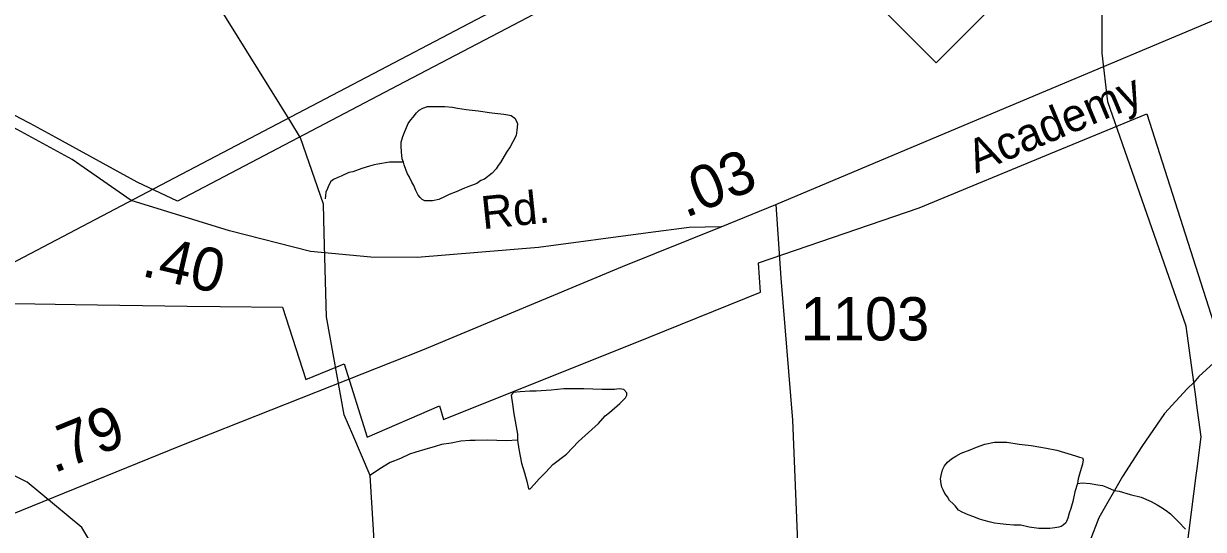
# Model space of a CAD drawing. Extents: x 2001466 to 2224147, y 644118 to 847247.
# Drawn here: x 2052246 to 2055654, y 665696 to 667157 of the extents above; entities that cross this region are included whole.
import ezdxf

# ---------------------------------------------------------------- set-up
doc = ezdxf.new("R2010")
doc.units = 0
for name, color, linetype in [('Exist Boundary Political City Limit New', 7, 'Continuous'), ('Exist Hydrographic Creek Single Shore', 7, 'Continuous'), ('Exist Hydrographic Misc Water Feature', 7, 'Continuous'), ('Exist Railroad Mainline', 7, 'Continuous'), ('Exist Road Primary NC Attributed', 7, 'Continuous'), ('Exist Road Primary NC Label', 7, 'Continuous'), ('Exist Road Primary NC Service Mileage Hundredths English Label', 7, 'Continuous'), ('Exist Road Primary NC Shield CELL', 7, 'Continuous'), ('Exist Road Secondary Mileage Hundredths English Label', 7, 'Continuous'), ('Exist Road Secondary Type 51 Attributed', 7, 'Continuous'), ('Exist Road Secondary Type 51 Label', 7, 'Continuous'), ('Exist Road Secondary Type 51 Number Label', 7, 'Continuous'), ('Map Preparation Boundary City Limit Buffer Line', 7, 'Continuous')]:
    doc.layers.add(name, color=color, linetype=linetype)

msp = doc.modelspace()

# ---------------------------------------------------------------- linework, layer by layer
at = {"layer": 'Exist Boundary Political City Limit New'}
for points in [[(2054801.8, 667751.5), (2053660.4, 667152.6), (2053327.5, 666977.9), (2052690.6, 666643.7), (2052574.2, 666699.1), (2052338.9, 666828.2), (2052265, 666867.9), (2052235.1, 666884), (2052099.1, 666957.6), (2052098.8, 666888.7), (2052095.1, 666691.8)], [(2052095.1, 666691.8), (2052092, 666502.8), (2052090.8, 666445.9), (2052123.5, 666350), (2052220.5, 666348.5), (2052394.6, 666345.8), (2052718.4, 666340.8), (2052814, 666339.7), (2052993.8, 666337.4), (2053061.5, 666128.9), (2053171.9, 666173.9), (2053238.5, 665962.8), (2053447.8, 666053.3), (2053459.1, 666013.7), (2054053.1, 666251.2), (2054374.5, 666381.3), (2054368.9, 666466.1), (2054832.8, 666624.4), (2055228.8, 666788.4), (2055490.1, 666895.9), (2055727.8, 666155.1)]]:
    msp.add_lwpolyline(points, dxfattribs=at)
at = {"layer": 'Exist Hydrographic Creek Single Shore'}
for points in [[(2053017.7, 666872.7), (2052736.4, 667325.2), (2052319.3, 667793), (2052143.4, 668082), (2051868.4, 668350), (2051451.4, 668630.9), (2051117.3, 668781.9), (2050292.4, 668952.9), (2050134.3, 669028.3), (2049975.4, 669271), (2049847.4, 669402.6)], [(2053114.6, 666551.6), (2053112.3, 666635.1), (2053046.3, 666826.8), (2053017.7, 666872.7)], [(2053273.2, 665427.7), (2053006.3, 665420.1), (2052782.4, 665359), (2052490.4, 665574.9), (2052414.3, 665701.1), (2052256.4, 665832.3), (2052022.2, 665948.5), (2051756.3, 665950.7), (2051539.3, 665974.8), (2051155.3, 666107.3), (2050197.3, 666481), (2049997.3, 666488.4), (2049843.6, 666575.6)], [(2053197.2, 665968.7), (2053172.4, 666027), (2053121.3, 666310.1), (2053114.6, 666551.6)], [(2053273.2, 665427.7), (2053247.2, 665851.5), (2053197.2, 665968.7)]]:
    msp.add_lwpolyline(points, dxfattribs=at)
at = {"layer": 'Exist Hydrographic Misc Water Feature'}
for p, q in [((2055632.7, 666072.1), (2055607.1, 666261.8)), ((2055634.1, 666061.9), (2055632.7, 666072.1)), ((2055633.2, 665852), (2055635.7, 665871.8))]:
    msp.add_line(p, q, dxfattribs=at)
for points in [[(2055607.1, 666261.8), (2055604.3, 666282.6), (2055378.3, 666930.3), (2055361.3, 667071.7), (2055367.4, 668505.3), (2055335.1, 668528.9)], [(2053343.2, 666756.6), (2053339.3, 666766.6), (2053337.2, 666786.6), (2053337, 666802.6), (2053337, 666814.6), (2053341.1, 666830.7), (2053345, 666840.7), (2053356.9, 666868.6), (2053364.9, 666878.7), (2053370.9, 666886.7), (2053380.9, 666898.7), (2053388.9, 666906.7), (2053398.9, 666912.8), (2053412.9, 666916.8), (2053436.9, 666916.8), (2053462.7, 666916.8), (2053484.9, 666914.9), (2053499, 666912.9), (2053524.8, 666908.9), (2053558.9, 666905), (2053598.9, 666899.1), (2053632.9, 666895.2), (2053645, 666893.2), (2053654.8, 666891.2), (2053664.9, 666883.3), (2053669, 666877.3), (2053672.9, 666867.3), (2053670.8, 666849.3), (2053669, 666833.3), (2053659.2, 666815.3), (2053651.2, 666801.2), (2053641.1, 666785.2), (2053623.3, 666755.2), (2053617.1, 666747.2), (2053611.2, 666737.2), (2053599.3, 666725.2), (2053577.1, 666707.1), (2053567.1, 666703.1), (2053555.4, 666695.1), (2053539.4, 666689), (2053529.4, 666685), (2053519.3, 666681), (2053495.3, 666671), (2053475.2, 666662.9), (2053463.3, 666656.9), (2053445.3, 666648.9), (2053427.4, 666644.8), (2053415.3, 666644.8), (2053405.5, 666644.8), (2053397.5, 666648.8), (2053391.4, 666654.8), (2053385.4, 666660.8), (2053379.3, 666674.8), (2053373.3, 666688.8), (2053367.4, 666698.7), (2053359.4, 666714.7), (2053355.3, 666722.7), (2053351.2, 666732.7), (2053345.2, 666748.7), (2053343.2, 666756.6)], [(2053343.2, 666756.6), (2053303.2, 666756.6), (2053269.1, 666750.5), (2053259.1, 666748.5), (2053245.2, 666744.5), (2053223.2, 666738.4), (2053197.4, 666728.4), (2053185.3, 666726.4), (2053163.3, 666716.3), (2053153.3, 666712.3), (2053141.4, 666706.3), (2053133.4, 666700.2), (2053127.3, 666690.2), (2053123.4, 666680.3), (2053119.5, 666670.3), (2053117.4, 666650.3)], [(2053672.5, 665953.4), (2053676.6, 665927.5), (2053684.6, 665887.5), (2053692.8, 665859.5), (2053700.8, 665831.5), (2053704.9, 665813.5), (2053708.8, 665813.5), (2053720.9, 665825.5), (2053734.8, 665841.6), (2053754.7, 665861.6), (2053774.6, 665883.6), (2053814.6, 665913.7), (2053848.6, 665949.8), (2053906.4, 666001.8), (2053926.3, 666023.9), (2053938.4, 666033.9), (2053968.4, 666060), (2053984.4, 666076), (2053988.3, 666084), (2053988.3, 666090), (2053980.3, 666100), (2053966.3, 666102), (2053952.4, 666099.9), (2053916.3, 666099.9), (2053864.2, 666101.7), (2053824.2, 666101.7), (2053806.4, 666101.6), (2053770.3, 666097.6), (2053726.2, 666095.5), (2053708.4, 666095.4), (2053680.3, 666093.4), (2053660.4, 666091.4), (2053654.4, 666083.4), (2053658.3, 666057.4), (2053662.4, 666029.4), (2053672.5, 665971.4), (2053672.5, 665953.4)], [(2055635.7, 665871.8), (2055647.3, 665963.5), (2055634.1, 666061.9)], [(2053672.5, 665953.4), (2053640.5, 665951.4), (2053584.7, 665953.3), (2053550.7, 665953.2), (2053534.7, 665953.2), (2053508.6, 665951.1), (2053480.8, 665945.1), (2053452.7, 665941), (2053434.6, 665935), (2053404.7, 665926.9), (2053378.6, 665918.9), (2053360.6, 665912.9), (2053334.8, 665900.8), (2053304.8, 665888.8), (2053274.9, 665870.7), (2053245, 665850.6)], [(2055290.5, 665828.5), (2055282.6, 665804.5), (2055276.6, 665776.5), (2055270.7, 665756.4), (2055266.6, 665742.4), (2055262.7, 665728.5), (2055258.6, 665718.5), (2055256.7, 665714.5), (2055248.7, 665708.4), (2055242.8, 665704.4), (2055236.8, 665702.4), (2055224.7, 665700.4), (2055210.8, 665698.4), (2055198.7, 665698.3), (2055178.8, 665698.3), (2055150.7, 665702.3), (2055126.7, 665708.2), (2055106.8, 665708.2), (2055084.7, 665710.1), (2055066.8, 665712.1), (2055050.8, 665714), (2055034.8, 665718), (2055020.7, 665722), (2055006.8, 665726), (2054990.8, 665731.9), (2054974.8, 665737.9), (2054956.7, 665745.9), (2054946.7, 665751.9), (2054936.6, 665763.9), (2054930.7, 665769.8), (2054920.6, 665779.8), (2054914.7, 665789.8), (2054906.7, 665799.8), (2054902.6, 665809.8), (2054898.7, 665817.8), (2054896.4, 665827.7), (2054894.6, 665841.7), (2054896.4, 665851.7), (2054900.5, 665867.7), (2054906.5, 665879.7), (2054914.5, 665889.7), (2054926.4, 665899.8), (2054938.5, 665907.8), (2054954.5, 665915.9), (2054980.3, 665925.9), (2054998.4, 665933.9), (2055022.3, 665942), (2055050.2, 665948), (2055086.3, 665948.1), (2055122.2, 665942.1), (2055156.2, 665938.2), (2055200.3, 665930.3), (2055230.3, 665924.4), (2055284.4, 665908.4), (2055296.5, 665904.5), (2055304.5, 665902.5), (2055306.3, 665896.5), (2055304.5, 665884.5), (2055298.3, 665862.5), (2055292.6, 665842.5), (2055290.5, 665828.5)], [(2055635.4, 664865.6), (2055590.3, 664924.6), (2055532.3, 665057.1), (2055633.2, 665852)], [(2055290.5, 665828.5), (2055304.5, 665830.5), (2055326.4, 665828.6), (2055348.6, 665824.6), (2055362.5, 665822.6), (2055376.5, 665816.6), (2055396.6, 665808.7), (2055410.5, 665806.7), (2055442.5, 665796.7), (2055474.5, 665788.8), (2055502.6, 665776.9), (2055520.4, 665766.9), (2055530.5, 665761), (2055546.7, 665751), (2055558.6, 665741), (2055566.5, 665733), (2055572.7, 665727), (2055580.7, 665719.1), (2055602.6, 665697.1)]]:
    msp.add_lwpolyline(points, dxfattribs=at)
at = {"layer": 'Exist Railroad Mainline'}
for points in [[(2046464.5, 663426.2), (2046524.6, 663459.1), (2048551.7, 664535.4), (2049194.6, 664876.7), (2049524.4, 665051.8), (2049557.2, 665070.3), (2052622.8, 666680.7), (2055671.2, 668278.9), (2056997.6, 668963.3), (2058840.6, 669936.5)], [(2055727.1, 666216.2), (2055641.1, 666137.7), (2055626.1, 666120.2), (2055607.5, 666101.5), (2055541.4, 666030.4), (2055476, 665935.1), (2055420, 665849.1), (2055352.2, 665729.1), (2055300.2, 665594.9)]]:
    msp.add_lwpolyline(points, dxfattribs=at)
at = {"layer": 'Exist Road Primary NC Attributed'}
for points in [[(2054418.6, 666634.2), (2054907.9, 666840.5), (2055677.6, 667164.1), (2056184.6, 667373.6), (2056567.7, 667530.7), (2056727.8, 667592.5), (2056935, 667655.3), (2057139.1, 667701.4)], [(2054260.6, 666569.3), (2054418.6, 666634.2)], [(2050426, 664989), (2050469.1, 665011), (2050704.3, 665125.3), (2051044.1, 665262.3), (2051844.1, 665591.2), (2052698.6, 665937.8), (2053399.3, 666214.3), (2053976.4, 666455.2), (2054260.6, 666569.3)]]:
    msp.add_lwpolyline(points, dxfattribs=at)
at = {"layer": 'Exist Road Primary NC Shield CELL'}
msp.add_lwpolyline([(2054549.1, 667376.3), (2054882.1, 667709.3), (2055215.1, 667376.3), (2054882.1, 667043.3)], close=True, dxfattribs=at)
at = {"layer": 'Exist Road Secondary Type 51 Attributed'}
for points in [[(2052557.1, 666646.2), (2052386.3, 666764), (2052162.5, 666885.4), (2051899.2, 667023.8), (2051726.1, 667110.4), (2051482.2, 667211.8), (2051238.9, 667288.9), (2050792.4, 667405.1), (2050170.2, 667573.1), (2049959.6, 667625.9), (2049883.6, 667635.4), (2049783.3, 667640.7), (2049542.6, 667618.5), (2049242.3, 667606.9)], [(2054418.6, 666634.2), (2054432.9, 666421.6), (2054466.7, 666011.7), (2054484.6, 665587.1), (2054486.7, 665225.8), (2054483.6, 665090.6), (2054443.4, 664991.3), (2054312.6, 664780.1), (2054253.4, 664718.8), (2053998, 664560.4), (2053751, 664429.4), (2053496.5, 664373.7), (2053164.1, 664331.2), (2052683.1, 664272.6), (2052013.9, 664187.6)], [(2054260.6, 666569.3), (2054168.1, 666567.5), (2054049.9, 666552.7), (2053733.2, 666510.4), (2053382.8, 666480.9), (2053249.3, 666481.9), (2053075.1, 666498.8), (2052840.7, 666558), (2052557.1, 666646.2)]]:
    msp.add_lwpolyline(points, dxfattribs=at)
at = {"layer": 'Map Preparation Boundary City Limit Buffer Line'}
for points in [[(2054801.8, 667751.5), (2053660.4, 667152.6), (2053327.5, 666977.9), (2052690.6, 666643.7), (2052574.2, 666699.1), (2052338.9, 666828.2), (2052265, 666867.9), (2052235.1, 666884), (2052099.1, 666957.6), (2052098.8, 666888.7), (2052095.1, 666691.8)], [(2052095.1, 666691.8), (2052092, 666502.8), (2052090.8, 666445.9), (2052123.5, 666350), (2052220.5, 666348.5), (2052394.6, 666345.8), (2052718.4, 666340.8), (2052814, 666339.7), (2052993.8, 666337.4), (2053061.5, 666128.9), (2053171.9, 666173.9), (2053238.5, 665962.8), (2053447.8, 666053.3), (2053459.1, 666013.7), (2054053.1, 666251.2), (2054374.5, 666381.3), (2054368.9, 666466.1), (2054832.8, 666624.4), (2055228.8, 666788.4), (2055490.1, 666895.9), (2055727.8, 666155.1)]]:
    msp.add_lwpolyline(points, dxfattribs=at)

# ---------------------------------------------------------------- texts
at = {"layer": 'Exist Road Primary NC Label'}
msp.add_text('Academy', height=95, rotation=22.7014, dxfattribs=at).set_placement((2054996.8, 666723.4))
at = {"layer": 'Exist Road Primary NC Service Mileage Hundredths English Label'}
for s, rotation, p in [('.03', 22.3367, (2054158, 666594.7)), ('.79', 22.0808, (2052333.6, 665857.2))]:
    msp.add_text(s, height=125, rotation=rotation, dxfattribs=at).set_placement(p)
at = {"layer": 'Exist Road Secondary Mileage Hundredths English Label'}
msp.add_text('.40', height=125, rotation=346.9481, dxfattribs=at).set_placement((2052583.3, 666428.7))
at = {"layer": 'Exist Road Secondary Type 51 Label'}
msp.add_text('Rd.', height=95, rotation=5.9087, dxfattribs=at).set_placement((2053572.6, 666562.7))
at = {"layer": 'Exist Road Secondary Type 51 Number Label'}
msp.add_text('1103', height=125, dxfattribs=at).set_placement((2054490.3, 666241.7))

doc.saveas('drawing.dxf')
